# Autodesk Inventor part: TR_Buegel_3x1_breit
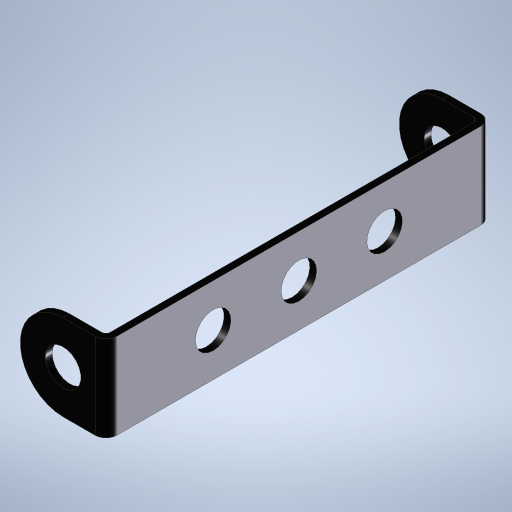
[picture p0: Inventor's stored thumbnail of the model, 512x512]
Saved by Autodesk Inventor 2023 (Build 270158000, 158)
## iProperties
Created: 2023-11
Part Number: TR_Buegel_3x1_breit
Material: Edelstahl
Document SubType Name: Modeling
Designer: Admin
Density: 8 g/cm^3
Appearance: Halbpoliert
Author: Admin
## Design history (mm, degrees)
sketch "Skizze1"
  geometry: L1 (10, 22.5)-(1.25, 22.5); L2 (0, 21.25)-(0, -21.25); L3 (1.25, -22.5)-(10, -22.5); L4 (10, -22.5)-(10, -21.7); L5 (10, -21.7)-(1.25, -21.7); L6 (0.8, -21.25)-(0.8, 21.25); L7 (1.25, 21.7)-(10, 21.7); L8 (10, 21.7)-(10, 22.5); A1 r 1.25 centre (1.25, 21.25) between (1.25, 22.5) and (0, 21.25); A2 r 1.25 centre (1.25, -21.25) between (0, -21.25) and (1.25, -22.5); A3 r 0.45 centre (1.25, 21.25) between (1.25, 21.7) and (0.8, 21.25); A4 r 0.45 centre (1.25, -21.25) between (0.8, -21.25) and (1.25, -21.7); 5 further points
  constraints: 16 end point, 8 point on circle, 8 tangent, 4 centre point, 4 point on line, 3 horizontal, 3 perpendicular, 2 equal radius, 2 midpoint, 2 vertical alignment, 1 coincident, 1 collinear, 1 horizontal alignment, 1 parallel, 1 vertical
  dimensions: "d0" = 0.8 distance of L7.end L1.start (= Dicke); "d1" = 10 horizontal distance of point (0, 0) L1.start (= Einheitsmaß); "d2" = 0.8 horizontal distance of point (0, 0) point (0.8, 21.7) (= Dicke); "d6" = 1.25 radius of A1; "d7" = 45 distance of L3.end L1.start (computed from Einheitsmaß, BreitLoch)
extrude "Extrusion1" new body sketch "Skizze1" stored distance "d8" = 10 (= Einheitsmaß); taper "d9" = 0 deg
fillet "Rundung1" dims "d10" = 5 (= 0.5 x Einheitsmaß)
sketch "Skizze2"
  geometry: C1 r 2.075 at (-5, 0); A1 r 5 centre (-5, 0) between (-5, 5) and (-5, -5) reference; 1 further point
  constraints: 1 centre point, 1 coincident
  dimensions: "d11" = 4.15 diameter of C1 (= 2 x Radius)
extrude "Extrusion2" cut sketch "Skizze2" extent not by distance; stored distance "d12" = 0; taper "d13" = 0 deg
sketch "Skizze3"
  geometry: C1 r 2.075 at (0, 0); 1 further point
  constraints: 1 centre point, 1 coincident
  dimensions: "d14" = 4.15 diameter of C1 (= 2 x Radius)
extrude "Extrusion3" cut sketch "Skizze3" extent not by distance; stored distance "d15" = 0; taper "d16" = 0 deg
pattern_linear "Rechteckige Anordnung2" dims "d22" = 10 (= Einheitsmaß)
node "Volumenkörper1"
other parameters: "Einheitsmaß" = 10 [user parameter; used in 5 equation terms], "Radius" = 2.075 [user parameter; used in 2 equation terms], "Fasen" = 0.5 [user parameter], "Dicke" = 0.8 [user parameter; used in 2 equation terms]
